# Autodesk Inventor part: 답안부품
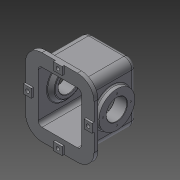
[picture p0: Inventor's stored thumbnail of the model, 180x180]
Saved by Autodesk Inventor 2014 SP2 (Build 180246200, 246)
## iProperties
Created: 2014-11
Part Number: 답안부품
Material: 일반
Document SubType Name: Modeling
Designer: 201-07
Density: 1 g/cm^3
Appearance: 기본값
Author: 201-07
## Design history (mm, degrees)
sketch "스케치1"
  geometry: L1 (87, 98)-(-87, 98); L2 (-87, 98)-(-87, -98); L3 (-87, -98)-(87, -98); L4 (87, -98)-(87, 98); L5 (87, 98)-(-87, -98); L6 (-87, 98)-(87, -98); 1 further point
  constraints: 12 end point, 2 midpoint, 2 parallel, 1 horizontal, 1 perpendicular
  dimensions: "d0" = 174 distance of L3.end L2.end; "d1" = 196 distance of L2.end L1.end
extrude "돌출1" new body sketch "스케치1" distance "d2" = 10; taper "d3" = 0 deg
sketch "스케치2"
  geometry: L1 (-65, 76)-(65, 76); L2 (65, 76)-(65, -76); L3 (65, -76)-(-65, -76); L4 (-65, -76)-(-65, 76); L5 (-65, 76)-(65, -76); L6 (65, 76)-(-65, -76); 1 further point
  constraints: 12 end point, 2 midpoint, 2 parallel, 1 horizontal, 1 perpendicular
  dimensions: "d4" = 130 distance of L2.end L3.end; "d5" = 152 distance of L1.end L2.end
extrude "돌출2" new body sketch "스케치2" distance "d6" = 118; taper "d7" = 0 deg
sketch "스케치3"
  geometry: L1 (-87, 98)-(87, 98) reference; L2 (-87, -98)-(-87, 98) reference; L3 (87, -98)-(-87, -98) reference; L4 (-87, 11)-(-67, 11); L5 (-67, 11)-(-67, -11); L6 (-67, -11)-(-87, -11); L7 (-87, -11)-(-87, 11); L8 (0, 98)-(0, -98); L9 (87, 11)-(67, 11); L10 (67, 11)-(67, -11); L11 (67, -11)-(87, -11); L12 (87, -11)-(87, 11); L13 (-87, 0)-(87, 0); L14 (-11, 98)-(11, 98); L15 (11, 98)-(11, 78); L16 (11, 78)-(-11, 78); L17 (-11, 78)-(-11, 98); L18 (11, -98)-(11, -78); L19 (11, -78)-(-11, -78); L20 (-11, -98)-(11, -98); L21 (-11, -78)-(-11, -98); 6 further points
  constraints: 36 end point, 10 symmetric about line, 7 midpoint, 4 parallel, 2 horizontal, 2 perpendicular, 1 collinear, 1 horizontal alignment, 1 point on line, 1 vertical alignment
  dimensions: "d8" = 20 distance of L4.start L4.end; "d9" = 22 distance of L4.end L5.end; "d10" = 22 distance of L15.end L16.end; "d11" = 20 distance of L14.end L15.end
extrude "돌출3" join sketch "스케치3" distance "d12" = 5; taper "d13" = 0 deg
sketch "스케치4"
  geometry: L1 (87, -15)-(65, -15) reference; L2 (87, -10)-(174, -10) reference; C1 r 45.5 at (76, 58); 2 further points
  constraints: 1 centre point, 1 midpoint, 1 vertical alignment
  dimensions: "d14" = 91 diameter of C1; "d83" = 68 distance from line of L2 C1.centre
extrude "돌출4" join sketch "스케치4" distance "d16" = 12; taper "d17" = 0 deg
fillet "모깎기1" dims "d18" = 42
fillet "모깎기2" dims "d19" = 20
fillet "모깎기3" dims "d20" = 10
feature "쉘1" dims "d21" = 10
sketch "스케치6"
  geometry: L1 (-45, 66)-(45, 66) reference; L2 (55, 56)-(55, -56) reference; L3 (45, -66)-(-45, -66) reference; L4 (-55, -56)-(-55, 56) reference; L5 (65, -56)-(65, 56) reference; L6 (45, 76)-(-45, 76) reference; L7 (-65, 56)-(-65, -56) reference; L8 (-45, -76)-(45, -76) reference; A1 r 10 centre (-45, 56) between (-45, 66) and (-55, 56) reference; A2 r 10 centre (45, 56) between (55, 56) and (45, 66) reference; A3 r 10 centre (45, -56) between (45, -66) and (55, -56) reference; A4 r 10 centre (-45, -56) between (-55, -56) and (-45, -66) reference; A5 r 20 centre (45, -56) between (45, -76) and (65, -56) reference; A6 r 20 centre (45, 56) between (65, 56) and (45, 76) reference; A7 r 20 centre (-45, 56) between (-45, 76) and (-65, 56) reference; A8 r 20 centre (-45, -56) between (-65, -56) and (-45, -76) reference
extrude "돌출5" cut sketch "스케치6" stored distance "d22" = 12; taper "d23" = 0 deg
sketch "스케치7"
  geometry: C1 r 45.5 at (56, 58) reference; 1 further point
  node "투영된 루프2"
node "작업 평면1"
sketch "스케치9"
  geometry: C1 r 35.5 at (56, 58); C2 r 45.5 at (56, 58) reference; 1 further point
  constraints: 1 centre point, 1 concentric
  dimensions: "d25" = 71 diameter of C1
feature "로프트1" sketch "스케치9" dims "d26" = 0, "d27" = 90 deg, "d28" = 0, "d29" = 90 deg
feature "결합1"
  node "솔리드2"
sketch "스케치10"
  geometry: C1 r 45.5 at (0, 0) reference; C2 r 26 at (0, 0); 1 further point
  constraints: 1 centre point, 1 coincident
  dimensions: "d30" = 52 diameter of C2
extrude "돌출6" cut sketch "스케치10" distance "d31" = 32; taper "d32" = 0 deg
sketch "스케치12"
  geometry: L1 (68, 0)-(152.121, -17.88); L2 (152.121, -17.88)-(158.566, 12.442); L3 (158.566, 12.442)-(124.445, 19.695); L4 (118, -10.628)-(124.445, 19.695); L5 (118, -56)-(118, 56) reference; L6 (68, -1.176)-(68, -26); 1 further point
  constraints: 10 end point, 3 perpendicular, 2 point on line, 1 parallel, 1 vertical alignment, 1 other
  dimensions: "d39" = 86 distance of L1.start L1.end; "d42" = 62 diameter of L2.end L1; "d43" = 78 deg angle of L6 L1
revolve "회전1" sketch "스케치12" stored, may be unused: angle "d44" = 90 deg
sketch "스케치13"
  geometry: L1 (-10, 10)-(-10, 122) reference; L2 (90, 0)-(0, 0); L3 (100, 122)-(100, 10) reference; L4 (0, 132)-(90, 132) reference; L5 (14, 55.372)-(76, 55.372) reference; L6 (-10, 10)-(-10, 122) reference; L7 (90, 0)-(0, 0) reference; L8 (100, 122)-(100, 10) reference; L9 (0, 132)-(90, 132) reference; A1 r 10 centre (0, 122) between (0, 132) and (-10, 122) reference; A2 r 10 centre (0, 10) between (-10, 10) and (0, 0) reference; A3 r 10 centre (90, 10) between (90, 0) and (100, 10) reference; A4 r 10 centre (90, 122) between (100, 122) and (90, 132) reference; A5 r 10 centre (0, 122) between (0, 132) and (-10, 122) reference; A6 r 10 centre (0, 10) between (-10, 10) and (0, 0) reference; A7 r 10 centre (90, 10) between (90, 0) and (100, 10) reference; A8 r 10 centre (90, 122) between (100, 122) and (90, 132) reference; 1 further point; 1 other entity
  constraints: 2 end point, 1 other
extrude "돌출7" cut sketch "스케치13" distance "d45" = 10; taper "d46" = 0 deg
sketch "스케치14"
  geometry: C1 r 31 at (0, 0) reference; 2 further points
  constraints: 1 coincident
hole "구멍1" sketch "스케치14" at (0, 0) diameter "d47" = 30; stored, may be unused: countersink angle "d51" = 90 deg, drill point angle "d53" = 118 deg; dims "d48" = 6, "d49" = 42, "d50" = 25, "d52" = 8
sketch "스케치15"
  geometry: L1 (-65, -56)-(-65, 56) reference; L2 (-45, 76)-(45, 76) reference; L3 (65, 56)-(65, -56) reference; L4 (45, -76)-(-45, -76) reference; L5 (-87, 56)-(-87, -56) reference; L6 (-45, -98)-(45, -98) reference; L7 (87, -56)-(87, 56) reference; L8 (45, 98)-(-45, 98) reference; L9 (-77, 0)-(77, 0); L10 (0, 88)-(0, -88); L11 (87, -56)-(87, 56) reference; A1 r 20 centre (-45, 56) between (-45, 76) and (-65, 56) reference; A2 r 20 centre (45, 56) between (65, 56) and (45, 76) reference; A3 r 20 centre (45, -56) between (45, -76) and (65, -56) reference; A4 r 20 centre (-45, -56) between (-65, -56) and (-45, -76) reference; A5 r 42 centre (-45, 56) between (-45, 98) and (-87, 56) reference; A6 r 42 centre (-45, -56) between (-87, -56) and (-45, -98) reference; A7 r 42 centre (45, -56) between (45, -98) and (87, -56) reference; A8 r 42 centre (45, 56) between (87, 56) and (45, 98) reference; 3 further points
  constraints: 4 coincident, 4 end point, 2 midpoint, 2 parallel, 1 perpendicular
  dimensions: "d77" = 176 distance of L10.end L10.start; "d78" = 10 distance from line of L11 L9.end
hole "구멍2" sketch "스케치15" at (77, 0), (-77, 0), (0, 88), (0, -88) diameter "d58" = 9; stored, may be unused: countersink angle "d62" = 90 deg, drill point angle "d64" = 118 deg; dims "d59" = 6, "d60" = 14, "d61" = 8.6, "d63" = 8
sketch "스케치16" dims "d65" = 70
  geometry: C1 r 26 at (0, 0) reference; C2 r 45.5 at (0, 0) reference; 6 further points
  constraints: 2 vertical alignment, 1 coincident, 7 other
  dimensions: "d68" = 360 deg dimension on C1.centre point (0, 35) (derived)
hole "구멍3" sketch "스케치16" at (0, 35), (-35, 0), (0, -35), (35, 0) diameter "d70" = 3.242; stored, may be unused: countersink angle "d74" = 90 deg, drill point angle "d76" = 118 deg; dims "d71" = 13, "d72" = 14, "d73" = 8.6, "d75" = 16
chamfer "모따기1" distance "d79" = 1; stored, may be unused: second distance "d80" = 2, angle "d81" = 45 deg
fillet "모깎기4" dims "d82" = 0.3
fillet "모깎기5" dims "d84" = 3
sketch "스케치17"
  geometry: L1 (56, -118)-(90, -118) reference; L2 (56, -123)-(34, -123) reference; 2 further points
  constraints: 1 midpoint, 1 vertical alignment, 1 other
  dimensions: "d85" = 92 distance from line of L1 point (45, -26)
feature "엠보싱1" sketch "스케치17" dims "d0" = 174, "d1" = 196, "d86" = 1, "d87" = 0
fillet "모깎기6" dims "d88" = 3
node "솔리드1"
mirror "대칭2"
mirror "대칭3"
node "투영된 루프1"
node "투영된 루프3"
node "투영된 루프4"
node "투영된 루프5"
